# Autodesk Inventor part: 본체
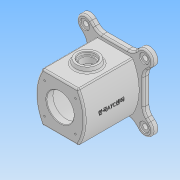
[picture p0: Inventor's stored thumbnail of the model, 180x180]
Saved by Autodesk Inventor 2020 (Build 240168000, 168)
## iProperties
Created: 2022-01
Part Number: 본체
Material: 일반
Document SubType Name: Modeling
Designer: user
Density: 1 g/cm^3
Appearance: 기본값
Mass: 457.865 g
Surface Area: 908.043 cm^2
Volume: 457.865 cm^3
Author: user
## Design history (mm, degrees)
sketch "스케치1"
  geometry: L1 (-32.942, 45)-(32.942, 45); L2 (32.942, -45)-(-32.942, -45); L3 (-45, 45)-(45, -45); L4 (45, 45)-(-45, -45); A1 r 90 centre (45, 0) between (-32.942, 45) and (-32.942, -45); A2 r 90 centre (-45, 0) between (32.942, -45) and (32.942, 45); 4 further points
  constraints: 8 end point, 6 point on circle, 3 vertical alignment, 2 centre point, 2 midpoint, 1 horizontal, 1 parallel, 1 perpendicular
  dimensions: "d0" = 90 distance of L3.end L4.end; "d1" = 90 distance of L4.start L3.end; "d3" = 90 radius of A1; "d4" = 90 radius of A2; "d5" = 45 deg angle of L1 L3; "d6" = 90 distance between parallel lines of L1 L2; "d7" = 45 distance from line of point (0, 0) L1; "d8" = 0 distance from line of L4.start L1; "d9" = 31.81981 distance from line of point (45, 0) L3; "d10" = 31.81981 distance from line of A1.centre L3; "d11" = 0 distance from line of L3.start L1; "d12" = 45 distance from line of point (-45, 0) L1; "d13" = 46.00271 distance from line of point (-45, -1.003) L1
extrude "돌출1" new body sketch "스케치1" stored distance "d14" = 110; taper "d15" = 0 deg
sketch "스케치2"
  geometry: L1 (-53, 53)-(53, 53); L2 (53, 53)-(53, -53); L3 (53, -53)-(-53, -53); L4 (-53, -53)-(-53, 53); L5 (-53, 53)-(53, -53); L6 (53, 53)-(-53, -53); L7 (0, 0)-(-54.447, 54.447); L8 (-42.493, 63.507)-(10.507, 10.507); L9 (-65.054, 43.841)-(-10.607, -10.607); L10 (-63.507, -42.493)-(-10.507, 10.507); L11 (-43.841, -65.054)-(10.607, -10.607); L12 (42.493, -63.507)-(-10.507, -10.507); L13 (65.054, -43.841)-(10.607, 10.607); L14 (63.507, 42.493)-(10.507, -10.507); L15 (43.841, 65.054)-(-10.607, 10.607); A1 r 15 centre (-54.447, 54.447) between (-42.493, 63.507) and (-65.054, 43.841); A2 r 15 centre (-54.447, -54.447) between (-63.507, -42.493) and (-43.841, -65.054); A3 r 15 centre (54.447, -54.447) between (42.493, -63.507) and (65.054, -43.841); A4 r 15 centre (54.447, 54.447) between (63.507, 42.493) and (43.841, 65.054); 8 further points
  constraints: 30 end point, 8 point on circle, 4 centre point, 3 perpendicular, 3 point on line, 2 midpoint, 2 parallel, 1 coincident, 1 horizontal, 1 tangent, 33 other
  dimensions: "d16" = 106 distance of L2.end L3.end; "d17" = 106 distance of L1.end L2.end; "d18" = 77 distance of L7.start L7.end; "d19" = 30 diameter of A1; "d22" = 360 deg dimension on L7.start A1.centre (derived)
extrude "돌출2" join sketch "스케치2" distance "d24" = 10; taper "d25" = 0 deg
sketch "스케치3"
  geometry: C1 r 25 at (0, 0); 1 further point
  constraints: 1 centre point, 1 coincident
  dimensions: "d26" = 50 diameter of C1
extrude "돌출3" cut sketch "스케치3" distance "d27" = 12; taper "d28" = 0 deg
sketch "스케치4"
  geometry: C1 r 25 at (0, 0) reference; 2 further points
  constraints: 1 coincident
hole "구멍1" sketch "스케치4" at (0, 0) diameter "d29" = 74; stored, may be unused: countersink angle "d33" = 90 deg, drill point angle "d35" = 0 deg; dims "d30" = 6, "d31" = 4, "d32" = 2, "d34" = 86
sketch "스케치5"
  geometry: C1 r 25.532 at (0, 0); 1 further point
  constraints: 1 centre point, 1 coincident
hole "구멍2" sketch "스케치5" at (0, 0) diameter "d36" = 50; stored, may be unused: countersink angle "d40" = 90 deg, drill point angle "d42" = 0 deg; dims "d37" = 6, "d38" = 4, "d39" = 2, "d41" = 12
node "작업 평면1"
sketch "스케치6"
  geometry: L1 (69.447, -55)-(69.447, -45) reference; L2 (69.447, -50)-(-69.447, -50); L3 (-69.447, -55)-(-69.447, -45) reference; L4 (0, -50)-(0, 5); C1 r 20 at (0, 5); 1 further point
  constraints: 4 end point, 3 midpoint, 1 centre point, 1 coincident, 1 vertical
  dimensions: "d44" = 55 distance of L4.start L4.end; "d45" = 40 diameter of C1
extrude "돌출4" join sketch "스케치6" stored distance "d46" = 12; taper "d47" = 15 deg
sketch "스케치7"
  geometry: C1 r 20 at (0, 0) reference; 2 further points
  constraints: 1 coincident
hole "구멍3" sketch "스케치7" at (0, 0) diameter "d48" = 30; stored, may be unused: countersink angle "d52" = 90 deg, drill point angle "d54" = 0 deg; dims "d49" = 6, "d50" = 4, "d51" = 2, "d53" = 5
sketch "스케치8"
  geometry: C1 r 15 at (0, 0) reference; 2 further points
  constraints: 1 coincident
hole "구멍4" sketch "스케치8" at (0, 0) diameter "d55" = 24; stored, may be unused: countersink angle "d59" = 90 deg, drill point angle "d61" = 0 deg; dims "d56" = 6, "d57" = 4, "d58" = 2, "d60" = 20
sketch "스케치9"
  geometry: A1 r 15 centre (-54.447, 54.447) between (-43.841, 65.054) and (-63.507, 42.493) reference; A2 r 15 centre (54.447, 54.447) between (65.054, 43.841) and (42.493, 63.507) reference; A3 r 15 centre (54.447, -54.447) between (43.841, -65.054) and (63.507, -42.493) reference; A4 r 15 centre (-54.447, -54.447) between (-65.054, -43.841) and (-42.493, -63.507) reference; 5 further points
  constraints: 4 coincident
hole "구멍5" sketch "스케치9" at (-54.447, 54.447), (54.447, 54.447), (54.447, -54.447), (-54.447, -54.447) diameter "d62" = 18; stored, may be unused: countersink angle "d66" = 90 deg, drill point angle "d68" = 0 deg; dims "d63" = 6, "d64" = 4, "d65" = 2, "d67" = 2
sketch "스케치10"
  geometry: C1 r 9 at (0, 0) reference; C2 r 9 at (0, 108.894) reference; C3 r 9 at (-108.894, 108.894) reference; C4 r 9 at (-108.894, 0) reference; 5 further points
  constraints: 4 coincident
hole "구멍6" sketch "스케치10" at (0, 0), (0, 108.894), (-108.894, 108.894), (-108.894, 0) diameter "d69" = 9; stored, may be unused: countersink angle "d73" = 90 deg, drill point angle "d75" = 0 deg; dims "d70" = 6, "d71" = 4, "d72" = 2, "d74" = 2
sketch "스케치11"
  geometry: L1 (0, 0)-(28.284, 28.284); L2 (0, 0)-(40, 0); C1 r 25 at (0, 0) reference
  constraints: 4 end point, 1 equal length, 1 horizontal
  dimensions: "d76" = 40 distance of L1.start L1.end; "d77" = 45 deg angle of L2 L1
hole "구멍7" sketch "스케치11" at (28.284, 28.284) diameter "d78" = 3.242; stored, may be unused: countersink angle "d82" = 90 deg, drill point angle "d84" = 118 deg; dims "d79" = 8, "d80" = 4, "d81" = 2, "d83" = 10
sketch "스케치12"
  geometry: L1 (0, 0)-(28.284, 28.284); L2 (0, 0)-(40, 0); C1 r 25 at (0, 0) reference
  constraints: 4 end point, 1 equal length, 1 horizontal
  dimensions: "d88" = 40 distance of L1.start L1.end; "d89" = 45 deg angle of L2 L1
hole "구멍8" sketch "스케치12" at (28.284, 28.284) diameter "d90" = 3.242; stored, may be unused: countersink angle "d94" = 90 deg, drill point angle "d96" = 118 deg; dims "d91" = 8, "d92" = 4, "d93" = 2, "d95" = 10
fillet "모깎기1" dims "d100" = 20
fillet "모깎기2" dims "d101" = 3
fillet "모깎기3" dims "d102" = 3
fillet "모깎기4" dims "d103" = 3
fillet "모깎기5" dims "d104" = 3
chamfer "모따기1" distance "d105" = 1; stored, may be unused: second distance "d106" = 2, angle "d107" = 45 deg
chamfer "모따기2" distance "d108" = 1; stored, may be unused: second distance "d109" = 2, angle "d110" = 45 deg
chamfer "모따기3" distance "d111" = 1; stored, may be unused: second distance "d112" = 2, angle "d113" = 45 deg
fillet "모깎기6" dims "d114" = 3
sketch "스케치15"
  geometry: L1 (53, -11)-(53, 21) reference; L2 (25, -54)-(-25, -54) reference; 2 further points
  constraints: 1 other
  dimensions: "d117" = 53 distance from line of L1 point (0, 6); "d118" = 60 distance from line of L2 point (0, 6)
feature "엠보싱1" sketch "스케치15" dims "d0" = 90, "d1" = 90, "d3" = 90, "d4" = 90, "d5" = 45 deg, "d6" = 90, "d7" = 45, "d8" = 0, "d9" = 31.81981, "d10" = 31.81981, "d11" = 0, "d12" = 45, "d13" = 46.00271, "d16" = 106, "d17" = 106, "d18" = 77, "d19" = 30, "d22" = 360 deg (derived), "d115" = 0.5, "d116" = 0
node "솔리드1"
pattern_circular "원형 패턴1" dims angle "d86" = 360 deg
pattern_circular "원형 패턴2" dims angle "d98" = 360 deg
feature "A9D066F2-1C7D-4E18-AEED-F7BC21143FA4" dims "d29" = 74, "d30" = 6, "d31" = 4, "d32" = 2, "d33" = 90 deg, "d34" = 86, "d35" = 0
other parameters: "d43" = 53
